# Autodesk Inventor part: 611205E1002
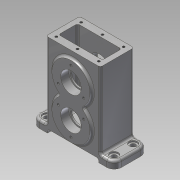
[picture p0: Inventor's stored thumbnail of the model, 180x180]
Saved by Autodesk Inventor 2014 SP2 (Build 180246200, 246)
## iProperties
Created: 2021-12
Part Number: 611205E1002
Material: 강철
Document SubType Name: Modeling
Designer: 거성
Density: 7.85 g/cm^3
Appearance: 강철
Author: 거성
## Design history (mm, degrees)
sketch "스케치1"
  geometry: L1 (-56, -5)-(-35, -5); L2 (-35, -5)-(-35, 0); L3 (-35, 0)-(35, 0); L4 (35, 0)-(35, -5); L5 (35, -5)-(56, -5); L6 (-56, -5)-(-56, 5); L7 (-56, 5)-(-37, 5); L8 (-37, 5)-(-37, 109); L9 (-37, 109)-(37, 109); L10 (37, 109)-(37, 5); L11 (37, 5)-(56, 5); L12 (56, 5)-(56, -5); 3 further points
  constraints: 24 end point, 6 parallel, 3 perpendicular, 2 collinear, 2 midpoint, 1 coincident, 1 horizontal, 1 horizontal alignment, 1 vertical alignment
  dimensions: "d0" = 112 distance between parallel lines of L12 L6; "d1" = 70 distance of L2.end L3.end; "d2" = 10 distance between parallel lines of L1 L7; "d3" = 10 distance between parallel lines of L11 L5; "d4" = 114 distance between parallel lines of L9 L5; "d5" = 5 distance of L1.end L2.end; "d6" = 21 distance of L1.start L1.end; "d7" = 74 distance between parallel lines of L10 L8
extrude "돌출1" new body sketch "스케치1" stored distance "d8" = 46; taper "d9" = 0 deg
sketch "스케치2"
  geometry: L1 (109, -23)-(0, -23) reference; L2 (0, -23)-(0, 23) reference; L3 (0, 23)-(109, 23) reference; L4 (109, 23)-(109, -23) reference; L5 (8, 13)-(109, 13); L6 (109, 13)-(109, -13); L7 (109, -13)-(8, -13); L8 (8, -13)-(8, 13); 3 further points
  constraints: 8 end point, 2 midpoint, 2 parallel, 1 coincident, 1 horizontal, 1 perpendicular
  dimensions: "d10" = 26 distance between parallel lines of L5 L7; "d11" = 10 distance between parallel lines of L1 L7; "d12" = 8 distance between parallel lines of L2 L8
extrude "돌출2" cut sketch "스케치2" stored distance "d13" = 60; taper "d14" = 0 deg
sketch "스케치3"
  geometry: L1 (-35, 0)-(35, 0) reference; L2 (35, -5)-(56, -5) reference; C1 r 26 at (0, 74); C2 r 26 at (0, 29); 4 further points
  constraints: 3 midpoint, 2 centre point, 2 vertical alignment
  dimensions: "d15" = 34 distance from line of C2.centre L2; "d16" = 79 distance from line of C1.centre L2; "d17" = 52 diameter of C1; "d18" = 52 diameter of C2
extrude "돌출3" join sketch "스케치3" distance "d19" = 3; taper "d20" = 0 deg
sketch "스케치4"
  geometry: C1 r 12 at (0, 74); C2 r 14 at (0, 74); C3 r 12 at (0, 29); C4 r 14 at (0, 29); A1 r 26 centre (0, 74) between (13.029, 51.5) and (-13.029, 51.5) reference; A2 r 26 centre (0, 29) between (-13.029, 51.5) and (13.029, 51.5) reference; 1 further point
  constraints: 4 centre point, 4 coincident
  dimensions: "d21" = 28 diameter of C2; "d22" = 24 diameter of C1; "d23" = 28 diameter of C4; "d24" = 24 diameter of C3
extrude "돌출4" cut sketch "스케치4" stored distance "d25" = 3; taper "d26" = 0 deg
extrude "돌출5" cut sketch "스케치4" distance "d27" = 11; taper "d28" = 0 deg
sketch "스케치5"
  geometry: C1 r 12 at (0, 74) reference; C2 r 12 at (0, 29) reference; C3 r 26 at (0, 74); C4 r 26 at (0, 29); 1 further point
  constraints: 2 centre point, 2 coincident
  dimensions: "d29" = 52 diameter of C3; "d30" = 52 diameter of C4
extrude "돌출6" join sketch "스케치5" distance "d31" = 3; taper "d32" = 0 deg
sketch "스케치6"
  geometry: C1 r 12 at (0, 29) reference; C2 r 16 at (0, 74); C3 r 14 at (0, 29); C4 r 14 at (0, 74); A1 r 26 centre (0, 74) between (13.029, 51.5) and (-13.029, 51.5) reference; A2 r 26 centre (0, 29) between (-13.029, 51.5) and (13.029, 51.5) reference; 1 further point
  constraints: 3 centre point, 3 coincident
  dimensions: "d33" = 28 diameter of C3; "d34" = 32 diameter of C2; "d35" = 28 diameter of C4
extrude "돌출7" cut sketch "스케치6" distance "d36" = 11; taper "d37" = 0 deg
extrude "돌출8" cut sketch "스케치6" distance "d38" = 20; taper "d39" = 0 deg
fillet "모깎기1" dims "d40" = 3, "d41" = 10
fillet "모깎기2" dims "d42" = 3
sketch "스케치7" dims "d43" = 40
  geometry: A1 r 26 centre (0, 74) between (16.403, 53.828) and (-16.403, 53.828) reference; 3 further points
  constraints: 2 vertical alignment, 1 coincident, 2 other
hole "구멍1" sketch "스케치7" at (0, 94) diameter "d44" = 3.242; stored, may be unused: countersink angle "d48" = 90 deg, drill point angle "d50" = 118 deg; dims "d45" = 8, "d46" = 4, "d47" = 2, "d49" = 10
sketch "스케치8" dims "d54" = 40
  geometry: C1 r 14 at (0, 29) reference; A1 r 26 centre (0, 29) between (-16.403, 49.172) and (16.403, 49.172) reference; 3 further points
  constraints: 2 vertical alignment, 1 coincident, 2 other
hole "구멍2" sketch "스케치8" at (0, 9) diameter "d55" = 3.242; stored, may be unused: countersink angle "d59" = 90 deg, drill point angle "d61" = 118 deg; dims "d56" = 8, "d57" = 4, "d58" = 2, "d60" = 10
sketch "스케치9" dims "d65" = 40, "d66" = 40
  geometry: C1 r 16 at (0, 74) reference; C2 r 14 at (0, 29) reference; A1 r 26 centre (0, 29) between (-16.403, 49.172) and (16.403, 49.172) reference; 5 further points
  constraints: 4 vertical alignment, 2 coincident, 4 other
hole "구멍3" sketch "스케치9" diameter "d67" = 3.242; stored, may be unused: countersink angle "d71" = 90 deg, drill point angle "d73" = 118 deg; dims "d68" = 8, "d69" = 4, "d70" = 2, "d72" = 10
hole "구멍4" sketch "스케치9" diameter "d77" = 3.242; stored, may be unused: countersink angle "d81" = 90 deg, drill point angle "d83" = 118 deg; dims "d78" = 8, "d79" = 4, "d80" = 2, "d82" = 10
sketch "스케치10"
  geometry: L1 (0, 0)-(68, 0) reference; L2 (-3, -3)-(-3, -43) reference; L3 (68, -46)-(0, -46) reference; L4 (71, -3)-(71, -43) reference; 7 further points
  constraints: 4 horizontal alignment, 4 vertical alignment
  dimensions: "d87" = 6 distance from line of L1 point (5, -6); "d88" = 8 distance from line of L2 point (5, -6); "d89" = 6 distance from line of L3 point (5, -40); "d90" = 8 distance from line of L4 point (63, -6)
hole "구멍5" sketch "스케치10" at (5, -6), (34, -6), (63, -6), (63, -40), (34, -40), (5, -40) diameter "d91" = 3.242; stored, may be unused: countersink angle "d95" = 90 deg, drill point angle "d97" = 118 deg; dims "d92" = 8, "d93" = 4, "d94" = 2, "d96" = 10
sketch "스케치11"
  geometry: 2 further points
  constraints: 1 coincident
hole "구멍6" sketch "스케치11" at (-32, 23) diameter "d98" = 4.917; stored, may be unused: countersink angle "d102" = 90 deg, drill point angle "d104" = 118 deg; dims "d99" = 8, "d100" = 11, "d101" = 1, "d103" = 20
sketch "스케치12"
  geometry: L1 (-56.279, -43)-(-74.804, -43) reference; L2 (-80, -40)-(-86, -40) reference; L3 (-93, -7)-(-93, -33) reference; L4 (-86, 0)-(-80, 0) reference; L5 (-80, -40)-(-80, 0) reference; L6 (-30, -46)-(-50, -46) reference; L7 (-5.196, -43)-(-23.721, -43) reference; L8 (0, -40)-(0, 0) reference; L9 (-23.721, 3)-(-5.196, 3) reference; L10 (-50, 6)-(-30, 6) reference; L11 (-74.804, 3)-(-56.279, 3) reference; L12 (6, -40)-(0, -40) reference; L13 (13, -7)-(13, -33) reference; L14 (0, 0)-(6, 0) reference; C1 r 2.458 at (-40, -20) reference; A1 r 7 centre (-86, -33) between (-93, -33) and (-86, -40) reference; A2 r 7 centre (-86, -7) between (-86, 0) and (-93, -7) reference; A3 r 7 centre (6, -33) between (6, -40) and (13, -33) reference; A4 r 7 centre (6, -7) between (13, -7) and (6, 0) reference; 5 further points
  constraints: 4 coincident, 8 other
hole "구멍7" sketch "스케치12" at (-86, -7), (-86, -33), (6, -33), (6, -7) diameter "d105" = 6.6; stored, may be unused: countersink angle "d109" = 90 deg, drill point angle "d111" = 118 deg; dims "d106" = 8, "d107" = 11, "d108" = 2, "d110" = 20
node "솔리드1"
pattern_circular "원형 패턴1" dims angle "d52" = 360 deg
pattern_circular "원형 패턴2" dims angle "d63" = 360 deg
pattern_circular "원형 패턴3" dims angle "d75" = 360 deg
pattern_circular "원형 패턴4" dims angle "d85" = 360 deg
node "절단 모서리 투영1"
node "절단 모서리 투영2"
